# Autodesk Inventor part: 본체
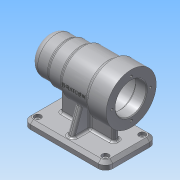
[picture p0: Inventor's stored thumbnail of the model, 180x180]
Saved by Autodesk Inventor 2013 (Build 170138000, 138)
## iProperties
Created: 2016-06
Part Number: 본체
Material: 알루미늄 6061
Document SubType Name: Modeling
Designer: Administrator
Density: 2.71 g/cm^3
Mass: 671.739 g
Surface Area: 646.329 cm^2
Volume: 247.874 cm^3
Author: Administrator
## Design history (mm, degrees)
sketch "스케치1"
  geometry: L1 (-46, 35)-(46, 35); L2 (56, 25)-(56, -25); L3 (46, -35)-(-46, -35); L4 (-56, -25)-(-56, 25); C1 r 2.5 at (-46, 25); C2 r 2.5 at (46, 25); C3 r 2.5 at (46, -25); C4 r 2.5 at (-46, -25); A1 r 10 centre (-46, 25) between (-46, 35) and (-56, 25); A2 r 10 centre (-46, -25) between (-56, -25) and (-46, -35); A3 r 10 centre (46, -25) between (46, -35) and (56, -25); A4 r 10 centre (46, 25) between (56, 25) and (46, 35); 3 further points
  constraints: 8 centre point, 8 end point, 8 point on circle, 8 tangent, 6 equal radius, 4 coincident, 2 midpoint, 2 parallel, 1 horizontal, 1 horizontal alignment, 1 perpendicular, 1 vertical alignment
  dimensions: "d0" = 112 distance between parallel lines of L2 L4; "d2" = 70 distance between parallel lines of L3 L1; "d3" = 10 radius of A1; "d4" = 5 diameter of C1
extrude "돌출1" new body sketch "스케치1" distance "d5" = 10; taper "d6" = 0 deg
sketch "스케치2"
  geometry: L1 (-56, 70)-(56, 70); L2 (-56, 70)-(-56, 104); L3 (-56, 104)-(-28, 104); L4 (-28, 104)-(-28, 100); L5 (-28, 100)-(11, 100); L6 (11, 100)-(11, 97); L7 (11, 97)-(31, 97); L8 (31, 97)-(31, 95); L9 (31, 95)-(56, 95); L10 (56, 95)-(56, 70); 2 further points
  constraints: 20 end point, 5 horizontal, 5 vertical, 1 vertical alignment
  dimensions: "d8" = 112 distance of L1.start L1.end; "d9" = 84 distance between parallel lines of L10 L4; "d10" = 45 distance between parallel lines of L10 L6; "d11" = 25 distance between parallel lines of L10 L8; "d12" = 68 diameter of L3 L1; "d13" = 60 diameter of L5 L1; "d14" = 54 diameter of L7 L1; "d15" = 50 diameter of L9 L1; "d16" = 70 vertical distance of point (0, 0) L1.end
revolve "회전1" sketch "스케치2" stored, may be unused: angle "d17" = 90 deg
sketch "스케치6"
  geometry: A1 r 34 centre (0, 0) between (-34, 0) and (-34, 0) reference; A2 r 26 centre (0, 0) between (-26, 0) and (26, 0); 3 further points
  constraints: 4 point on circle, 2 horizontal alignment, 2 vertical alignment, 1 centre point, 1 coincident
  dimensions: "d44" = 52 diameter of A2
hole "구멍1" sketch "스케치6" at (-26, 0), (26, 0), (0, -26), (0, 26) diameter "d46" = 3.242; stored, may be unused: countersink angle "d50" = 90 deg, drill point angle "d52" = 118 deg; dims "d47" = 8, "d48" = 4, "d49" = 2, "d51" = 11
hole "구멍2" diameter "d55" = 5; stored, may be unused: countersink angle "d59" = 90 deg, drill point angle "d61" = 0 deg; dims "d53" = 10, "d54" = 10, "d56" = 8, "d57" = 9, "d58" = 4, "d60" = 11
hole "구멍3" diameter "d64" = 5; stored, may be unused: countersink angle "d68" = 90 deg, drill point angle "d70" = 0 deg; dims "d62" = 10, "d63" = 10, "d65" = 8, "d66" = 9, "d67" = 4, "d69" = 11
hole "구멍4" diameter "d73" = 5; stored, may be unused: countersink angle "d77" = 90 deg, drill point angle "d79" = 0 deg; dims "d71" = 10, "d72" = 10, "d74" = 8, "d75" = 9, "d76" = 4, "d78" = 11
hole "구멍5" diameter "d82" = 5; stored, may be unused: countersink angle "d86" = 90 deg, drill point angle "d88" = 0 deg; dims "d80" = 10, "d81" = 10, "d83" = 8, "d84" = 9, "d85" = 4, "d87" = 11
node "작업 평면1"
sketch "스케치7"
  geometry: L1 (47.5, 34)-(47.5, -34) reference; 3 further points
  constraints: 1 horizontal alignment, 1 midpoint, 1 other
  dimensions: "d89" = 48 distance from line of L1 point (-0.5, 0)
feature "엠보싱1" sketch "스케치7" dims "d0" = 112, "d2" = 70, "d3" = 10, "d4" = 5, "d90" = 0.5, "d91" = 0
fillet "모깎기1" dims "d92" = 3
fillet "모깎기2" dims "d93" = 10
sketch "스케치8"
  geometry: L1 (-36, 10.173)-(-36, 54); L2 (-36, 54)-(36, 54); L3 (36, 54)-(36, 10); L4 (-56, 0)-(-56, 10) reference; L5 (56, 0)-(56, 10) reference; L6 (-46, 10)-(-56, 10) reference; L7 (56, 10)-(46, 10) reference; 1 further point
  constraints: 6 end point, 2 vertical, 1 horizontal, 1 point on line
  dimensions: "d94" = 20 distance between parallel lines of L4 L1; "d95" = 20 distance between parallel lines of L5 L3; "d96" = 54 distance from line of point (0, 0) L2
extrude "돌출4" join sketch "스케치8" stored distance "d98" = 8; taper "d99" = 0 deg
sketch "스케치9"
  geometry: L1 (-35, 0)-(-35, 10) reference; L2 (-25, 10)-(-35, 10) reference; L3 (35, 10)-(25, 10) reference; L4 (35, 0)-(35, 10) reference; L5 (-28, 10)-(-11.985, 54); L6 (-11.985, 54)-(11.985, 54); L7 (11.985, 54)-(28, 10); 1 further point
  constraints: 6 end point, 2 point on line, 1 equal length, 1 horizontal
  dimensions: "d100" = 7 distance from line of L5.start L1; "d101" = 7 distance from line of L7.end L4; "d102" = 110 deg angle of L3 L7; "d103" = 54 distance from line of point (0, 0) L6
extrude "돌출5" join sketch "스케치9" stored distance "d105" = 8; taper "d106" = 0 deg
sketch "스케치10"
  geometry: L1 (-56, 36)-(-56, 104) reference; L2 (56, 85)-(56, 55) reference; L3 (-56, 70)-(56, 70); L4 (-56, 70)-(-56, 91); L5 (-41, 91)-(-41, 94); L6 (-41, 94)-(13, 94); L7 (13, 94)-(13, 91); L8 (13, 91)-(25, 91); L9 (25, 91)-(25, 87.5); L10 (25, 87.5)-(43, 87.5); L11 (43, 87.5)-(43, 86); L12 (43, 86)-(47, 86); L13 (47, 86)-(47, 80.5); L14 (47, 80.5)-(50, 80.5); L15 (50, 80.5)-(50, 70); L16 (-56, 91)-(-41, 91); 1 further point
  constraints: 28 end point, 6 horizontal, 6 vertical, 2 midpoint, 2 point on line
  dimensions: "d107" = 15 distance of L4.end L5.start; "d109" = 54 distance of L5.end L6.end; "d110" = 12 distance of L7.end L8.end; "d111" = 18 distance of L9.end L10.end; "d112" = 4 distance of L11.end L12.end; "d113" = 3 distance of L13.end L14.end; "d114" = 42 diameter of L16 L3; "d115" = 48 diameter of L6 L3; "d116" = 42 diameter of L8 L3; "d117" = 35 diameter of L10 L3; "d118" = 32 diameter of L12 L3; "d119" = 21 diameter of L14 L3
revolve "회전3" sketch "스케치10" stored, may be unused: angle "d120" = 90 deg
chamfer "모따기1" distance "d121" = 1; stored, may be unused: second distance "d122" = 2, angle "d123" = 45 deg
chamfer "모따기2" distance "d124" = 4; stored, may be unused: second distance "d125" = 2, angle "d126" = 45 deg
fillet "모깎기3" dims "d127" = 10
fillet "모깎기4" dims "d128" = 0.3
fillet "모깎기5" dims "d129" = 3
fillet "모깎기6" dims "d130" = 3
fillet "모깎기7" dims "d131" = 3
fillet "모깎기8" dims "d132" = 3
node "솔리드1"
other parameters: "d97" = 8, "d104" = 8
